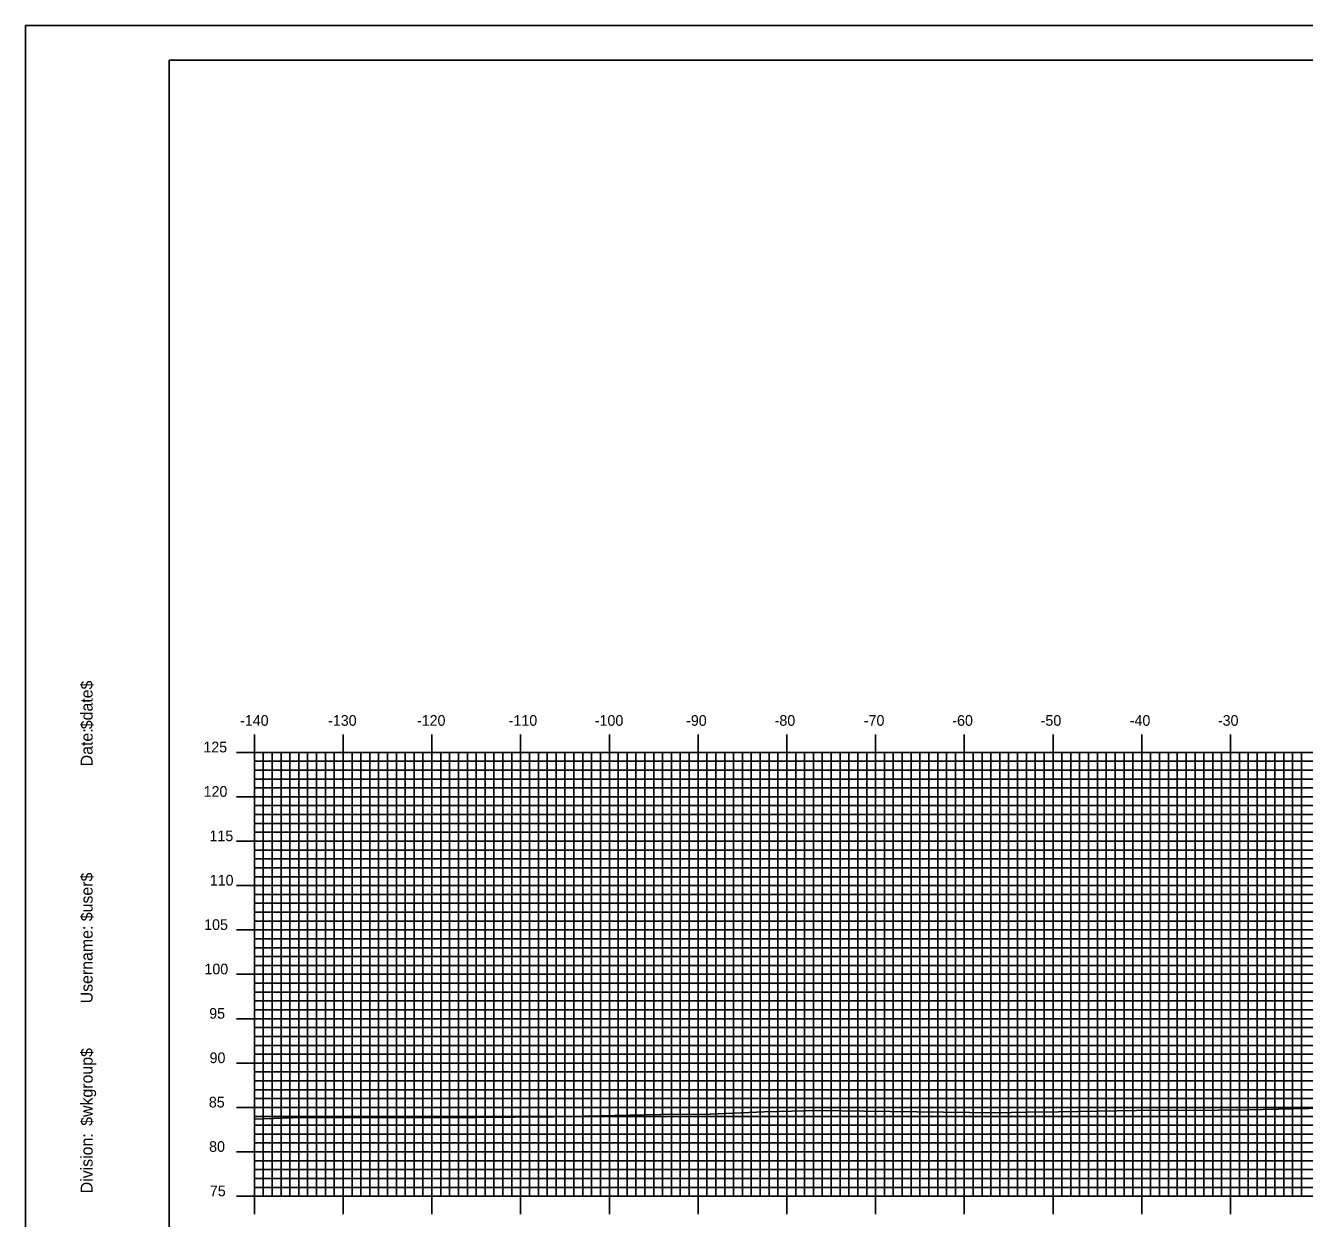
# Model space of a CAD drawing. Extents: x 92 to 435, y -1658 to -1438.
# Drawn here: x 91.8 to 236, y -1572.1 to -1437.7 of the extents above; entities that cross this region are included whole.
import ezdxf

# ---------------------------------------------------------------- set-up
doc = ezdxf.new("R2010")
doc.units = 0
for name, color, linetype in [('BORDER', 7, 'Continuous'), ('H_V ANNOTATION', 7, 'Continuous'), ('MAJOR', 7, 'Continuous'), ('MINOR', 7, 'Continuous'), ('PLOT BOUNDARY', 7, 'Continuous'), ('S_Roadway_Centerline', 7, 'Continuous')]:
    doc.layers.add(name, color=color, linetype=linetype)

msp = doc.modelspace()

# ---------------------------------------------------------------- linework, layer by layer
at = {"layer": 'BORDER'}
msp.add_lwpolyline([(108.02, -1651.6), (428.02, -1651.6), (428.02, -1441.6), (108.02, -1441.6)], close=True, dxfattribs=at)
at = {"layer": 'MAJOR'}
for p, q in [((117.62, -1517.6), (117.62, -1519.6)), ((127.62, -1517.6), (127.62, -1519.6)), ((137.62, -1517.6), (137.62, -1519.6)), ((147.62, -1517.6), (147.62, -1519.6)), ((157.62, -1517.6), (157.62, -1519.6)), ((167.62, -1517.6), (167.62, -1519.6)), ((177.62, -1517.6), (177.62, -1519.6)), ((187.62, -1517.6), (187.62, -1519.6)), ((197.62, -1517.6), (197.62, -1519.6)), ((207.62, -1517.6), (207.62, -1519.6)), ((217.62, -1517.6), (217.62, -1519.6)), ((227.62, -1517.6), (227.62, -1519.6)), ((115.62, -1519.6), (117.62, -1519.6)), ((117.62, -1519.6), (397.62, -1519.6)), ((117.62, -1569.6), (117.62, -1519.6)), ((117.62, -1569.6), (117.62, -1519.6)), ((117.62, -1519.6), (397.62, -1519.6)), ((127.62, -1569.6), (127.62, -1519.6)), ((137.62, -1569.6), (137.62, -1519.6)), ((147.62, -1569.6), (147.62, -1519.6)), ((157.62, -1569.6), (157.62, -1519.6)), ((167.62, -1569.6), (167.62, -1519.6)), ((177.62, -1569.6), (177.62, -1519.6)), ((187.62, -1569.6), (187.62, -1519.6)), ((197.62, -1569.6), (197.62, -1519.6)), ((207.62, -1569.6), (207.62, -1519.6)), ((217.62, -1569.6), (217.62, -1519.6)), ((227.62, -1569.6), (227.62, -1519.6)), ((115.62, -1524.6), (117.62, -1524.6)), ((117.62, -1524.6), (397.62, -1524.6)), ((115.62, -1529.6), (117.62, -1529.6)), ((117.62, -1529.6), (397.62, -1529.6)), ((115.62, -1534.6), (117.62, -1534.6)), ((117.62, -1534.6), (397.62, -1534.6)), ((115.62, -1539.6), (117.62, -1539.6)), ((117.62, -1539.6), (397.62, -1539.6)), ((115.62, -1544.6), (117.62, -1544.6)), ((117.62, -1544.6), (397.62, -1544.6)), ((115.62, -1549.6), (117.62, -1549.6)), ((117.62, -1549.6), (397.62, -1549.6)), ((115.62, -1554.6), (117.62, -1554.6)), ((117.62, -1554.6), (397.62, -1554.6)), ((115.62, -1559.6), (117.62, -1559.6)), ((117.62, -1559.6), (397.62, -1559.6)), ((115.62, -1564.6), (117.62, -1564.6)), ((117.62, -1564.6), (397.62, -1564.6)), ((115.62, -1569.6), (117.62, -1569.6)), ((117.62, -1569.6), (397.62, -1569.6)), ((117.62, -1569.6), (397.62, -1569.6)), ((117.62, -1571.61), (117.62, -1569.6)), ((127.62, -1571.61), (127.62, -1569.6)), ((137.62, -1571.61), (137.62, -1569.6)), ((147.62, -1571.61), (147.62, -1569.6)), ((157.62, -1571.61), (157.62, -1569.6)), ((167.62, -1571.61), (167.62, -1569.6)), ((177.62, -1571.61), (177.62, -1569.6)), ((187.62, -1571.61), (187.62, -1569.6)), ((197.62, -1571.61), (197.62, -1569.6)), ((207.62, -1571.61), (207.62, -1569.6)), ((217.62, -1571.61), (217.62, -1569.6)), ((227.62, -1571.61), (227.62, -1569.6))]:
    msp.add_line(p, q, dxfattribs=at)
at = {"layer": 'MINOR'}
for p, q in [((118.62, -1569.6), (118.62, -1519.6)), ((119.62, -1569.6), (119.62, -1519.6)), ((120.62, -1569.6), (120.62, -1519.6)), ((121.62, -1569.6), (121.62, -1519.6)), ((122.62, -1569.6), (122.62, -1519.6)), ((123.62, -1569.6), (123.62, -1519.6)), ((124.62, -1569.6), (124.62, -1519.6)), ((125.62, -1569.6), (125.62, -1519.6)), ((126.62, -1569.6), (126.62, -1519.6)), ((128.62, -1569.6), (128.62, -1519.6)), ((129.62, -1569.6), (129.62, -1519.6)), ((130.62, -1569.6), (130.62, -1519.6)), ((131.62, -1569.6), (131.62, -1519.6)), ((132.62, -1569.6), (132.62, -1519.6)), ((133.62, -1569.6), (133.62, -1519.6)), ((134.62, -1569.6), (134.62, -1519.6)), ((135.62, -1569.6), (135.62, -1519.6)), ((136.62, -1569.6), (136.62, -1519.6)), ((138.62, -1569.6), (138.62, -1519.6)), ((139.62, -1569.6), (139.62, -1519.6)), ((140.62, -1569.6), (140.62, -1519.6)), ((141.62, -1569.6), (141.62, -1519.6)), ((142.62, -1569.6), (142.62, -1519.6)), ((143.62, -1569.6), (143.62, -1519.6)), ((144.62, -1569.6), (144.62, -1519.6)), ((145.62, -1569.6), (145.62, -1519.6)), ((146.62, -1569.6), (146.62, -1519.6)), ((148.62, -1569.6), (148.62, -1519.6)), ((149.62, -1569.6), (149.62, -1519.6)), ((150.62, -1569.6), (150.62, -1519.6)), ((151.62, -1569.6), (151.62, -1519.6)), ((152.62, -1569.6), (152.62, -1519.6)), ((153.62, -1569.6), (153.62, -1519.6)), ((154.62, -1569.6), (154.62, -1519.6)), ((155.62, -1569.6), (155.62, -1519.6)), ((156.62, -1569.6), (156.62, -1519.6)), ((158.62, -1569.6), (158.62, -1519.6)), ((159.62, -1569.6), (159.62, -1519.6)), ((160.62, -1569.6), (160.62, -1519.6)), ((161.62, -1569.6), (161.62, -1519.6)), ((162.62, -1569.6), (162.62, -1519.6)), ((163.62, -1569.6), (163.62, -1519.6)), ((164.62, -1569.6), (164.62, -1519.6)), ((165.62, -1569.6), (165.62, -1519.6)), ((166.62, -1569.6), (166.62, -1519.6)), ((168.62, -1569.6), (168.62, -1519.6)), ((169.62, -1569.6), (169.62, -1519.6)), ((170.62, -1569.6), (170.62, -1519.6)), ((171.62, -1569.6), (171.62, -1519.6)), ((172.62, -1569.6), (172.62, -1519.6)), ((173.62, -1569.6), (173.62, -1519.6)), ((174.62, -1569.6), (174.62, -1519.6)), ((175.62, -1569.6), (175.62, -1519.6)), ((176.62, -1569.6), (176.62, -1519.6)), ((178.62, -1569.6), (178.62, -1519.6)), ((179.62, -1569.6), (179.62, -1519.6)), ((180.62, -1569.6), (180.62, -1519.6)), ((181.62, -1569.6), (181.62, -1519.6)), ((182.62, -1569.6), (182.62, -1519.6)), ((183.62, -1569.6), (183.62, -1519.6)), ((184.62, -1569.6), (184.62, -1519.6)), ((185.62, -1569.6), (185.62, -1519.6)), ((186.62, -1569.6), (186.62, -1519.6)), ((188.62, -1569.6), (188.62, -1519.6)), ((189.62, -1569.6), (189.62, -1519.6)), ((190.62, -1569.6), (190.62, -1519.6)), ((191.62, -1569.6), (191.62, -1519.6)), ((192.62, -1569.6), (192.62, -1519.6)), ((193.62, -1569.6), (193.62, -1519.6)), ((194.62, -1569.6), (194.62, -1519.6)), ((195.62, -1569.6), (195.62, -1519.6)), ((196.62, -1569.6), (196.62, -1519.6)), ((198.62, -1569.6), (198.62, -1519.6)), ((199.62, -1569.6), (199.62, -1519.6)), ((200.62, -1569.6), (200.62, -1519.6)), ((201.62, -1569.6), (201.62, -1519.6)), ((202.62, -1569.6), (202.62, -1519.6)), ((203.62, -1569.6), (203.62, -1519.6)), ((204.62, -1569.6), (204.62, -1519.6)), ((205.62, -1569.6), (205.62, -1519.6)), ((206.62, -1569.6), (206.62, -1519.6)), ((208.62, -1569.6), (208.62, -1519.6)), ((209.62, -1569.6), (209.62, -1519.6)), ((210.62, -1569.6), (210.62, -1519.6)), ((211.62, -1569.6), (211.62, -1519.6)), ((212.62, -1569.6), (212.62, -1519.6)), ((213.62, -1569.6), (213.62, -1519.6)), ((214.62, -1569.6), (214.62, -1519.6)), ((215.62, -1569.6), (215.62, -1519.6)), ((216.62, -1569.6), (216.62, -1519.6)), ((218.62, -1569.6), (218.62, -1519.6)), ((219.62, -1569.6), (219.62, -1519.6)), ((220.62, -1569.6), (220.62, -1519.6)), ((221.62, -1569.6), (221.62, -1519.6)), ((222.62, -1569.6), (222.62, -1519.6)), ((223.62, -1569.6), (223.62, -1519.6)), ((224.62, -1569.6), (224.62, -1519.6)), ((225.62, -1569.6), (225.62, -1519.6)), ((226.62, -1569.6), (226.62, -1519.6)), ((228.62, -1569.6), (228.62, -1519.6)), ((229.62, -1569.6), (229.62, -1519.6)), ((230.62, -1569.6), (230.62, -1519.6)), ((231.62, -1569.6), (231.62, -1519.6)), ((232.62, -1569.6), (232.62, -1519.6)), ((233.62, -1569.6), (233.62, -1519.6)), ((234.62, -1569.6), (234.62, -1519.6)), ((235.62, -1569.6), (235.62, -1519.6)), ((117.62, -1520.6), (397.62, -1520.6)), ((117.62, -1520.6), (119.63, -1520.6)), ((117.62, -1521.6), (397.62, -1521.6)), ((117.62, -1521.6), (119.63, -1521.6)), ((117.62, -1522.6), (397.62, -1522.6)), ((117.62, -1522.6), (119.63, -1522.6)), ((117.62, -1523.6), (397.62, -1523.6)), ((117.62, -1523.6), (119.63, -1523.6)), ((117.62, -1525.6), (397.62, -1525.6)), ((117.62, -1525.6), (119.63, -1525.6)), ((117.62, -1526.6), (397.62, -1526.6)), ((117.62, -1526.6), (119.63, -1526.6)), ((117.62, -1527.6), (397.62, -1527.6)), ((117.62, -1527.6), (119.63, -1527.6)), ((117.62, -1528.6), (397.62, -1528.6)), ((117.62, -1528.6), (119.63, -1528.6)), ((117.62, -1530.6), (397.62, -1530.6)), ((117.62, -1530.6), (119.63, -1530.6)), ((117.62, -1531.6), (397.62, -1531.6)), ((117.62, -1531.6), (119.63, -1531.6)), ((117.62, -1532.6), (397.62, -1532.6)), ((117.62, -1532.6), (119.63, -1532.6)), ((117.62, -1533.6), (397.62, -1533.6)), ((117.62, -1533.6), (119.63, -1533.6)), ((117.62, -1535.6), (397.62, -1535.6)), ((117.62, -1535.6), (119.63, -1535.6)), ((117.62, -1536.6), (397.62, -1536.6)), ((117.62, -1536.6), (119.63, -1536.6)), ((117.62, -1537.6), (397.62, -1537.6)), ((117.62, -1537.6), (119.63, -1537.6)), ((117.62, -1538.6), (397.62, -1538.6)), ((117.62, -1538.6), (119.63, -1538.6)), ((117.62, -1540.6), (397.62, -1540.6)), ((117.62, -1540.6), (119.63, -1540.6)), ((117.62, -1541.6), (397.62, -1541.6)), ((117.62, -1541.6), (119.63, -1541.6)), ((117.62, -1542.6), (397.62, -1542.6)), ((117.62, -1542.6), (119.63, -1542.6)), ((117.62, -1543.6), (397.62, -1543.6)), ((117.62, -1543.6), (119.63, -1543.6)), ((117.62, -1545.6), (397.62, -1545.6)), ((117.62, -1545.6), (119.63, -1545.6)), ((117.62, -1546.6), (397.62, -1546.6)), ((117.62, -1546.6), (119.63, -1546.6)), ((117.62, -1547.6), (397.62, -1547.6)), ((117.62, -1547.6), (119.63, -1547.6)), ((117.62, -1548.6), (397.62, -1548.6)), ((117.62, -1548.6), (119.63, -1548.6)), ((117.62, -1550.6), (397.62, -1550.6)), ((117.62, -1550.6), (119.63, -1550.6)), ((117.62, -1551.6), (397.62, -1551.6)), ((117.62, -1551.6), (119.63, -1551.6)), ((117.62, -1552.6), (397.62, -1552.6)), ((117.62, -1552.6), (119.63, -1552.6)), ((117.62, -1553.6), (397.62, -1553.6)), ((117.62, -1553.6), (119.63, -1553.6)), ((117.62, -1555.6), (397.62, -1555.6)), ((117.62, -1555.6), (119.63, -1555.6)), ((117.62, -1556.6), (397.62, -1556.6)), ((117.62, -1556.6), (119.63, -1556.6)), ((117.62, -1557.6), (397.62, -1557.6)), ((117.62, -1557.6), (119.63, -1557.6)), ((117.62, -1558.6), (397.62, -1558.6)), ((117.62, -1558.6), (119.63, -1558.6)), ((117.62, -1560.6), (397.62, -1560.6)), ((117.62, -1560.6), (119.63, -1560.6)), ((117.62, -1561.6), (397.62, -1561.6)), ((117.62, -1561.6), (119.63, -1561.6)), ((117.62, -1562.6), (397.62, -1562.6)), ((117.62, -1562.6), (119.63, -1562.6)), ((117.62, -1563.6), (397.62, -1563.6)), ((117.62, -1563.6), (119.63, -1563.6)), ((117.62, -1565.6), (397.62, -1565.6)), ((117.62, -1565.6), (119.63, -1565.6)), ((117.62, -1566.6), (397.62, -1566.6)), ((117.62, -1566.6), (119.63, -1566.6)), ((117.62, -1567.6), (397.62, -1567.6)), ((117.62, -1567.6), (119.63, -1567.6)), ((117.62, -1568.6), (397.62, -1568.6)), ((117.62, -1568.6), (119.63, -1568.6))]:
    msp.add_line(p, q, dxfattribs=at)
at = {"layer": 'PLOT BOUNDARY'}
msp.add_lwpolyline([(91.83, -1657.72), (431.83, -1657.72), (431.83, -1437.72), (91.83, -1437.72)], close=True, dxfattribs=at)
at = {"layer": 'S_Roadway_Centerline'}
msp.add_lwpolyline([(117.62, -1560.92), (121.92, -1560.78), (123.68, -1560.73), (125.83, -1560.74), (134.61, -1560.77), (142.7, -1560.74), (151.38, -1560.64), (163.41, -1560.41), (169.01, -1560.34), (175.05, -1560.08), (181.25, -1559.94), (186.32, -1560.02), (201.22, -1560.19), (204.58, -1560.13), (208.23, -1560.09), (217.02, -1559.94), (226.28, -1559.92), (229.62, -1559.88), (244.97, -1559.52)], dxfattribs=at)

# ---------------------------------------------------------------- texts
at = {"layer": 'BORDER'}
for s, p in [('$date$', (99.39, -1516.99)), ('Date:', (99.39, -1521.17)), ('$user$', (99.39, -1538.62)), ('Username:', (99.39, -1547.87)), ('$wkgroup$', (99.39, -1561.67)), ('Division:', (99.39, -1569.27))]:
    msp.add_text(s, height=1.339, rotation=90, dxfattribs=at).set_placement(p)
at = {"layer": 'H_V ANNOTATION'}
for s, p in [('-140', (116.01, -1516.6)), ('-130', (125.93, -1516.6)), ('-120', (135.94, -1516.6)), ('-110', (146.28, -1516.6)), ('-100', (155.98, -1516.6)), ('-90', (166.27, -1516.6)), ('-80', (176.25, -1516.6)), ('-70', (186.3, -1516.6)), ('-60', (196.27, -1516.6)), ('-50', (206.23, -1516.6)), ('-40', (216.27, -1516.6)), ('-30', (226.2, -1516.6)), ('125', (111.87, -1519.6)), ('120', (111.9, -1524.6)), ('115', (112.56, -1529.6)), ('110', (112.59, -1534.6)), ('105', (111.96, -1539.6)), ('100', (111.99, -1544.6)), ('95', (112.53, -1549.6)), ('90', (112.57, -1554.6)), ('85', (112.49, -1559.6)), ('80', (112.52, -1564.6)), ('75', (112.6, -1569.6))]:
    msp.add_text(s, height=1.2, dxfattribs=at).set_placement(p)
at = {"layer": 'MAJOR'}
msp.add_text('-', height=0.012, dxfattribs=at).set_placement((117.61, -1569.6))

doc.saveas('drawing.dxf')
